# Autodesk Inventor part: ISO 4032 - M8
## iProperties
Comments: To add or edit properties for Autodesk Inventor files, use iProperties.
Created: 2004-08
Part Number: ISO 4032 - M8
Vendor: Autodesk Inc.
Document SubType Name: Modeling
Designer: John Blackburn
Material: Default
Description: Hex Nut
Standard: ISO 4032
Size Designation: M8
Alert: To add or edit properties for Autodesk Inventor files, use iProperties.
Control State: 0
Master: False
Checked Out: False
Shininess: 64.0
Length Units: 11269
Angle Units: 11279
Time Units: 11290
Mass Units: 11283
Length Display Precision: 3
Angle Display Precision: 2
Compacted: True
EGR: 1
Density: 0.0
Volumn: 0.0
Area: 0.0
PropertySet Name: Model Information
Author: John Blackburn
Revision Number: 8
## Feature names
1. Body [Extrusion]
2. Chamfer1 [Revolution]
3. Thread [Hole]
4. Chamfer2
5. Chamfer3
